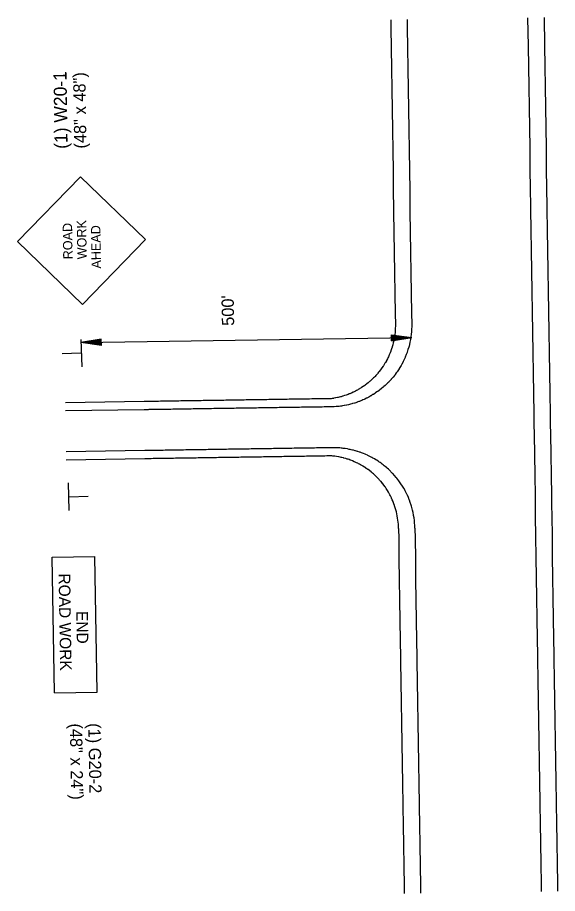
# Model space of a CAD drawing. Extents: x 1770139 to 1773492, y 718230 to 727190.
# Drawn here: x 1771613.4 to 1771877.5, y 720589.3 to 721017.8 of the extents above; entities that cross this region are included whole.
import ezdxf

# ---------------------------------------------------------------- set-up
doc = ezdxf.new("R2010")
doc.units = 0
for name, color, linetype in [('R_Dimension', 7, 'Continuous'), ('R_MOT', 7, 'Continuous'), ('R_Proposed Road', 7, 'Continuous')]:
    doc.layers.add(name, color=color, linetype=linetype)

msp = doc.modelspace()

# ---------------------------------------------------------------- linework, layer by layer
at = {"layer": 'R_Dimension'}
for p, q in [((1771644.44, 720858.82), (1771806.34, 720861.31)), ((1771796.32, 720862.66), (1771806.34, 720861.31)), ((1771796.37, 720859.66), (1771796.32, 720862.66)), ((1771796.32, 720862.41), (1771804.67, 720861.29)), ((1771796.33, 720862.15), (1771802.95, 720861.26)), ((1771796.33, 720861.9), (1771801.29, 720861.23)), ((1771796.34, 720861.65), (1771799.59, 720861.21)), ((1771796.34, 720861.39), (1771797.92, 720861.18)), ((1771796.35, 720860.41), (1771801.29, 720861.23)), ((1771796.35, 720860.67), (1771799.59, 720861.21)), ((1771796.35, 720860.92), (1771797.92, 720861.18)), ((1771796.36, 720859.91), (1771804.67, 720861.29)), ((1771796.36, 720860.16), (1771802.95, 720861.26)), ((1771796.37, 720859.66), (1771806.34, 720861.31)), ((1771654.42, 720860.47), (1771644.44, 720858.82)), ((1771654.47, 720857.47), (1771644.44, 720858.82)), ((1771654.42, 720860.22), (1771646.11, 720858.84)), ((1771654.46, 720857.72), (1771646.11, 720858.84)), ((1771654.43, 720859.97), (1771647.83, 720858.87)), ((1771654.46, 720857.98), (1771647.83, 720858.87)), ((1771654.43, 720859.72), (1771649.5, 720858.9)), ((1771654.45, 720858.23), (1771649.5, 720858.9)), ((1771654.44, 720859.46), (1771651.19, 720858.92)), ((1771654.45, 720858.49), (1771651.19, 720858.92)), ((1771654.44, 720859.21), (1771652.86, 720858.95)), ((1771654.45, 720858.74), (1771652.86, 720858.95)), ((1771654.47, 720857.47), (1771654.42, 720860.47))]:
    msp.add_line(p, q, dxfattribs=at)
at = {"layer": 'R_MOT'}
for p, q in [((1771644.22, 720939.98), (1771613.44, 720908.23)), ((1771644.22, 720939.98), (1771675.95, 720909.19)), ((1771675.95, 720909.19), (1771645.19, 720877.44)), ((1771613.44, 720908.23), (1771645.19, 720877.44)), ((1771644.39, 720860.4), (1771644.82, 720846.9)), ((1771644.41, 720853.68), (1771635.2, 720853.38)), ((1771638.67, 720776.74), (1771638.4, 720790.24)), ((1771638.73, 720783.46), (1771647.95, 720783.64)), ((1771630.46, 720753.86), (1771651.32, 720754.18)), ((1771652.34, 720687.77), (1771651.32, 720754.18)), ((1771631.48, 720687.45), (1771630.46, 720753.86)), ((1771631.48, 720687.45), (1771652.34, 720687.77))]:
    msp.add_line(p, q, dxfattribs=at)
at = {"layer": 'R_Proposed Road'}
for p, q in [((1771675.32, 720829.98), (1771636.83, 720829.39)), ((1771675.38, 720825.98), (1771636.89, 720825.39)), ((1771675.69, 720805.99), (1771637.2, 720805.39)), ((1771675.72, 720801.99), (1771637.26, 720801.39))]:
    msp.add_line(p, q, dxfattribs=at)
for points in [[(1771795.95, 721016.69), (1771796.01, 721012.86), (1771796.16, 721002.86), (1771796.31, 720992.87), (1771796.47, 720982.87), (1771796.62, 720972.87), (1771796.78, 720962.87), (1771796.93, 720952.87), (1771797.08, 720942.87), (1771797.24, 720932.87), (1771797.36, 720924.66), (1771797.36, 720924.65), (1771797.39, 720922.87), (1771797.55, 720912.88), (1771797.7, 720902.88), (1771797.85, 720892.88), (1771798.01, 720882.88), (1771798.16, 720872.88), (1771798.24, 720867.88)], [(1771803.95, 721016.82), (1771804, 721012.99), (1771804.16, 721002.99), (1771804.31, 720992.99), (1771804.47, 720982.99), (1771804.62, 720972.99), (1771804.77, 720962.99), (1771804.93, 720952.99), (1771805.08, 720943), (1771805.24, 720933), (1771805.36, 720924.78), (1771805.36, 720924.78), (1771805.39, 720923), (1771805.55, 720913), (1771805.7, 720903), (1771805.85, 720893), (1771806.01, 720883), (1771806.16, 720873), (1771806.24, 720868)], [(1771862.94, 721017.73), (1771863.15, 721003.9), (1771863.31, 720993.9), (1771863.46, 720983.9), (1771863.61, 720973.9), (1771863.77, 720963.9), (1771863.92, 720953.9), (1771864.08, 720943.9), (1771864.23, 720933.91), (1771864.36, 720925.69), (1771864.36, 720925.69), (1771864.38, 720923.91), (1771864.54, 720913.91), (1771864.69, 720903.91), (1771864.85, 720893.91), (1771865, 720883.91), (1771865.15, 720873.91), (1771865.31, 720863.91), (1771865.46, 720853.91), (1771865.62, 720843.92), (1771865.77, 720833.92), (1771865.92, 720823.92), (1771866, 720818.92), (1771866.08, 720813.92), (1771866.23, 720803.92), (1771866.39, 720793.92), (1771866.54, 720783.92), (1771866.61, 720779.2), (1771866.61, 720779.19), (1771866.69, 720773.92), (1771866.85, 720763.93), (1771867, 720753.93), (1771867.16, 720743.93), (1771867.31, 720733.93), (1771867.47, 720723.93), (1771867.62, 720713.93), (1771867.74, 720705.95), (1771867.77, 720703.93), (1771867.93, 720693.93), (1771868.08, 720683.93), (1771868.24, 720673.94), (1771868.39, 720663.94), (1771868.54, 720653.94), (1771868.7, 720643.94), (1771868.85, 720633.94), (1771868.87, 720632.7), (1771869.01, 720623.94), (1771869.16, 720613.94), (1771869.31, 720603.94), (1771869.47, 720593.95), (1771869.52, 720590.38)], [(1771870.94, 721017.85), (1771871.15, 721004.02), (1771871.3, 720994.02), (1771871.46, 720984.02), (1771871.61, 720974.02), (1771871.77, 720964.03), (1771871.92, 720954.03), (1771872.07, 720944.03), (1771872.23, 720934.03), (1771872.36, 720925.81), (1771872.36, 720925.81), (1771872.38, 720924.03), (1771872.54, 720914.03), (1771872.69, 720904.03), (1771872.85, 720894.03), (1771873, 720884.03), (1771873.15, 720874.04), (1771873.31, 720864.04), (1771873.46, 720854.04), (1771873.62, 720844.04), (1771873.77, 720834.04), (1771873.92, 720824.04), (1771874, 720819.04), (1771874.08, 720814.04), (1771874.23, 720804.04), (1771874.39, 720794.05), (1771874.54, 720784.05), (1771874.61, 720779.32), (1771874.61, 720779.32), (1771874.69, 720774.05), (1771874.85, 720764.05), (1771875, 720754.05), (1771875.16, 720744.05), (1771875.31, 720734.05), (1771875.46, 720724.05), (1771875.62, 720714.05), (1771875.74, 720706.07), (1771875.77, 720704.06), (1771875.93, 720694.06), (1771876.08, 720684.06), (1771876.23, 720674.06), (1771876.39, 720664.06), (1771876.54, 720654.06), (1771876.7, 720644.06), (1771876.85, 720634.06), (1771876.87, 720632.82), (1771877, 720624.07), (1771877.16, 720614.07), (1771877.31, 720604.07), (1771877.47, 720594.07), (1771877.52, 720590.5)], [(1771798.24, 720867.88), (1771798.24, 720866.86), (1771798.21, 720865.83), (1771798.16, 720864.8), (1771798.07, 720863.78), (1771797.97, 720862.82), (1771797.96, 720862.76), (1771797.82, 720861.74), (1771797.64, 720860.73), (1771797.44, 720859.72), (1771797.32, 720859.14), (1771797.22, 720858.71), (1771796.96, 720857.71), (1771796.67, 720856.72), (1771796.65, 720856.63), (1771796.36, 720855.73), (1771796.02, 720854.75), (1771795.96, 720854.61), (1771795.64, 720853.78), (1771795.27, 720852.88), (1771795.24, 720852.82), (1771794.82, 720851.87), (1771794.57, 720851.35), (1771794.36, 720850.93), (1771793.88, 720850), (1771793.86, 720849.97), (1771793.36, 720849.08), (1771793.14, 720848.71), (1771792.82, 720848.18), (1771792.42, 720847.54), (1771792.26, 720847.29), (1771791.69, 720846.46), (1771791.66, 720846.42), (1771791.04, 720845.56), (1771790.96, 720845.45), (1771790.39, 720844.71), (1771790.22, 720844.49), (1771790.06, 720844.3), (1771789.72, 720843.89), (1771789.47, 720843.6), (1771789.02, 720843.08), (1771788.72, 720842.75), (1771788.29, 720842.29), (1771787.96, 720841.95), (1771787.53, 720841.52), (1771787.2, 720841.19), (1771786.76, 720840.77), (1771786.43, 720840.47), (1771785.95, 720840.04), (1771785.66, 720839.78), (1771785.13, 720839.33), (1771784.87, 720839.13), (1771784.28, 720838.65), (1771784.09, 720838.51), (1771783.69, 720838.21), (1771783.4, 720837.99), (1771783.3, 720837.92), (1771782.5, 720837.36), (1771782.5, 720837.36), (1771781.7, 720836.82), (1771781.58, 720836.75), (1771780.89, 720836.32), (1771780.64, 720836.17), (1771780.08, 720835.84), (1771779.68, 720835.61), (1771779.26, 720835.38), (1771778.7, 720835.09), (1771778.44, 720834.96), (1771777.7, 720834.59), (1771777.61, 720834.55), (1771776.78, 720834.17), (1771776.68, 720834.12), (1771775.94, 720833.81), (1771775.64, 720833.69), (1771775.09, 720833.47), (1771774.58, 720833.28), (1771774.24, 720833.16), (1771773.51, 720832.91), (1771773.39, 720832.87), (1771772.52, 720832.6), (1771772.42, 720832.57), (1771771.66, 720832.35), (1771771.32, 720832.26), (1771770.79, 720832.13), (1771770.21, 720831.99), (1771769.91, 720831.93), (1771769.08, 720831.76), (1771769.03, 720831.75), (1771768.14, 720831.59), (1771767.94, 720831.56), (1771767.25, 720831.45), (1771766.8, 720831.39), (1771766.3, 720831.38), (1771765.3, 720831.37), (1771764.3, 720831.35), (1771763.3, 720831.34), (1771762.3, 720831.32), (1771761.3, 720831.31), (1771760.3, 720831.29), (1771759.3, 720831.28), (1771758.3, 720831.26), (1771757.3, 720831.25), (1771756.3, 720831.23), (1771755.3, 720831.22), (1771754.3, 720831.2), (1771753.3, 720831.18), (1771752.3, 720831.17), (1771751.3, 720831.15), (1771750.3, 720831.14), (1771749.3, 720831.12), (1771748.3, 720831.11), (1771747.3, 720831.09), (1771746.3, 720831.08), (1771745.3, 720831.06), (1771744.3, 720831.05), (1771743.3, 720831.03), (1771742.3, 720831.01), (1771741.3, 720831), (1771740.3, 720830.98), (1771739.3, 720830.97), (1771738.3, 720830.95), (1771737.3, 720830.94), (1771736.3, 720830.92), (1771735.3, 720830.91), (1771734.3, 720830.89), (1771733.3, 720830.88), (1771732.3, 720830.86), (1771731.3, 720830.85), (1771730.3, 720830.83), (1771729.3, 720830.81), (1771728.3, 720830.8), (1771727.3, 720830.78), (1771726.3, 720830.77), (1771725.3, 720830.75), (1771724.3, 720830.74), (1771723.3, 720830.72), (1771722.3, 720830.71), (1771721.3, 720830.69), (1771720.3, 720830.68), (1771719.3, 720830.66), (1771718.3, 720830.65), (1771717.3, 720830.63), (1771716.3, 720830.61), (1771715.3, 720830.6), (1771714.3, 720830.58), (1771713.3, 720830.57), (1771712.3, 720830.55), (1771711.3, 720830.54), (1771710.3, 720830.52), (1771709.3, 720830.51), (1771708.3, 720830.49), (1771707.3, 720830.48), (1771706.3, 720830.46), (1771705.3, 720830.44), (1771704.31, 720830.43), (1771703.31, 720830.41), (1771702.31, 720830.4), (1771701.31, 720830.38), (1771700.31, 720830.37), (1771699.31, 720830.35), (1771698.31, 720830.34), (1771697.31, 720830.32), (1771696.31, 720830.31), (1771695.31, 720830.29), (1771694.31, 720830.28), (1771693.31, 720830.26), (1771692.31, 720830.24), (1771691.31, 720830.23), (1771690.31, 720830.21), (1771689.31, 720830.2), (1771688.31, 720830.18), (1771687.31, 720830.17), (1771686.81, 720830.16), (1771686.31, 720830.15), (1771685.31, 720830.14), (1771684.31, 720830.12), (1771683.31, 720830.11), (1771682.31, 720830.09), (1771681.31, 720830.08), (1771680.31, 720830.06), (1771679.31, 720830.04), (1771678.31, 720830.03), (1771677.58, 720830.02), (1771677.31, 720830.01), (1771676.32, 720830), (1771675.32, 720829.98), (1771675.32, 720829.98)], [(1771806.24, 720868), (1771806.24, 720866.72), (1771806.2, 720865.44), (1771806.11, 720864.16), (1771805.99, 720862.88), (1771805.84, 720861.69), (1771805.82, 720861.61), (1771805.62, 720860.35), (1771805.37, 720859.09), (1771805.09, 720857.84), (1771804.91, 720857.13), (1771804.76, 720856.6), (1771804.39, 720855.37), (1771803.99, 720854.15), (1771803.95, 720854.05), (1771803.55, 720852.95), (1771803.06, 720851.76), (1771802.99, 720851.59), (1771802.54, 720850.59), (1771802.02, 720849.5), (1771801.99, 720849.43), (1771801.39, 720848.3), (1771801.05, 720847.68), (1771800.76, 720847.18), (1771800.1, 720846.09), (1771800.08, 720846.05), (1771799.4, 720845.01), (1771799.1, 720844.57), (1771798.66, 720843.96), (1771798.12, 720843.22), (1771797.9, 720842.93), (1771797.14, 720841.98), (1771797.1, 720841.93), (1771796.26, 720840.96), (1771796.16, 720840.83), (1771795.4, 720840.01), (1771795.17, 720839.76), (1771794.96, 720839.54), (1771794.51, 720839.09), (1771794.19, 720838.77), (1771793.59, 720838.19), (1771793.2, 720837.84), (1771792.64, 720837.33), (1771792.21, 720836.97), (1771791.66, 720836.5), (1771791.23, 720836.15), (1771790.66, 720835.7), (1771790.24, 720835.38), (1771789.63, 720834.94), (1771789.25, 720834.67), (1771788.58, 720834.2), (1771788.26, 720833.99), (1771787.5, 720833.51), (1771787.27, 720833.36), (1771786.77, 720833.06), (1771786.41, 720832.84), (1771786.28, 720832.77), (1771785.29, 720832.21), (1771785.29, 720832.21), (1771784.3, 720831.69), (1771784.15, 720831.62), (1771783.3, 720831.21), (1771783, 720831.07), (1771782.31, 720830.76), (1771781.82, 720830.55), (1771781.32, 720830.34), (1771780.63, 720830.07), (1771780.32, 720829.95), (1771779.43, 720829.62), (1771779.33, 720829.59), (1771778.33, 720829.26), (1771778.21, 720829.22), (1771777.34, 720828.96), (1771776.98, 720828.86), (1771776.34, 720828.68), (1771775.74, 720828.53), (1771775.34, 720828.44), (1771774.49, 720828.25), (1771774.35, 720828.22), (1771773.35, 720828.02), (1771773.23, 720828), (1771772.35, 720827.86), (1771771.97, 720827.8), (1771771.35, 720827.72), (1771770.7, 720827.64), (1771770.36, 720827.6), (1771769.42, 720827.51), (1771769.36, 720827.51), (1771768.36, 720827.44), (1771768.14, 720827.43), (1771767.36, 720827.4), (1771766.86, 720827.39), (1771766.36, 720827.38), (1771765.36, 720827.37), (1771764.36, 720827.35), (1771763.36, 720827.34), (1771762.36, 720827.32), (1771761.36, 720827.31), (1771760.36, 720827.29), (1771759.36, 720827.28), (1771758.36, 720827.26), (1771757.36, 720827.25), (1771756.36, 720827.23), (1771755.36, 720827.22), (1771754.36, 720827.2), (1771753.36, 720827.18), (1771752.36, 720827.17), (1771751.36, 720827.15), (1771750.36, 720827.14), (1771749.36, 720827.12), (1771748.36, 720827.11), (1771747.36, 720827.09), (1771746.36, 720827.08), (1771745.36, 720827.06), (1771744.36, 720827.05), (1771743.36, 720827.03), (1771742.36, 720827.02), (1771741.36, 720827), (1771740.36, 720826.98), (1771739.36, 720826.97), (1771738.36, 720826.95), (1771737.36, 720826.94), (1771736.36, 720826.92), (1771735.36, 720826.91), (1771734.36, 720826.89), (1771733.36, 720826.88), (1771732.36, 720826.86), (1771731.36, 720826.85), (1771730.36, 720826.83), (1771729.36, 720826.81), (1771728.36, 720826.8), (1771727.36, 720826.78), (1771726.36, 720826.77), (1771725.36, 720826.75), (1771724.36, 720826.74), (1771723.36, 720826.72), (1771722.36, 720826.71), (1771721.36, 720826.69), (1771720.36, 720826.68), (1771719.36, 720826.66), (1771718.36, 720826.65), (1771717.37, 720826.63), (1771716.37, 720826.61), (1771715.37, 720826.6), (1771714.37, 720826.58), (1771713.37, 720826.57), (1771712.37, 720826.55), (1771711.37, 720826.54), (1771710.37, 720826.52), (1771709.37, 720826.51), (1771708.37, 720826.49), (1771707.37, 720826.48), (1771706.37, 720826.46), (1771705.37, 720826.45), (1771704.37, 720826.43), (1771703.37, 720826.41), (1771702.37, 720826.4), (1771701.37, 720826.38), (1771700.37, 720826.37), (1771699.37, 720826.35), (1771698.37, 720826.34), (1771697.37, 720826.32), (1771696.37, 720826.31), (1771695.37, 720826.29), (1771694.37, 720826.28), (1771693.37, 720826.26), (1771692.37, 720826.24), (1771691.37, 720826.23), (1771690.37, 720826.21), (1771689.37, 720826.2), (1771688.37, 720826.18), (1771687.37, 720826.17), (1771686.87, 720826.16), (1771686.37, 720826.15), (1771685.37, 720826.14), (1771684.37, 720826.12), (1771683.37, 720826.11), (1771682.37, 720826.09), (1771681.37, 720826.08), (1771680.37, 720826.06), (1771679.37, 720826.04), (1771678.37, 720826.03), (1771677.64, 720826.02), (1771677.37, 720826.01), (1771676.38, 720826), (1771675.38, 720825.98)], [(1771807.78, 720768.02), (1771807.74, 720769.3), (1771807.66, 720770.58), (1771807.53, 720771.85), (1771807.37, 720773.13), (1771807.18, 720774.31), (1771807.17, 720774.39), (1771806.92, 720775.65), (1771806.64, 720776.9), (1771806.31, 720778.14), (1771806.11, 720778.84), (1771805.95, 720779.37), (1771805.55, 720780.59), (1771805.11, 720781.79), (1771805.06, 720781.9), (1771804.62, 720782.98), (1771804.11, 720784.15), (1771804.03, 720784.32), (1771803.55, 720785.31), (1771803, 720786.38), (1771802.96, 720786.45), (1771802.33, 720787.56), (1771801.97, 720788.17), (1771801.67, 720788.66), (1771800.97, 720789.74), (1771800.94, 720789.77), (1771800.23, 720790.79), (1771799.92, 720791.22), (1771799.47, 720791.82), (1771798.9, 720792.53), (1771798.67, 720792.82), (1771797.88, 720793.75), (1771797.84, 720793.8), (1771796.98, 720794.74), (1771796.86, 720794.86), (1771796.09, 720795.67), (1771795.85, 720795.9), (1771795.63, 720796.12), (1771795.16, 720796.56), (1771794.83, 720796.87), (1771794.22, 720797.42), (1771793.82, 720797.77), (1771793.24, 720798.25), (1771792.81, 720798.61), (1771792.24, 720799.05), (1771791.79, 720799.39), (1771791.21, 720799.82), (1771790.78, 720800.13), (1771790.16, 720800.56), (1771789.77, 720800.81), (1771789.09, 720801.26), (1771788.76, 720801.46), (1771787.99, 720801.92), (1771787.75, 720802.06), (1771787.25, 720802.34), (1771786.87, 720802.55), (1771786.74, 720802.62), (1771785.74, 720803.14), (1771785.74, 720803.15), (1771784.73, 720803.63), (1771784.58, 720803.7), (1771783.72, 720804.09), (1771783.41, 720804.22), (1771782.71, 720804.51), (1771782.22, 720804.7), (1771781.71, 720804.9), (1771781.02, 720805.15), (1771780.7, 720805.26), (1771779.8, 720805.55), (1771779.7, 720805.58), (1771778.69, 720805.88), (1771778.57, 720805.92), (1771777.69, 720806.15), (1771777.33, 720806.24), (1771776.68, 720806.4), (1771776.08, 720806.53), (1771775.68, 720806.61), (1771774.82, 720806.78), (1771774.68, 720806.8), (1771773.67, 720806.96), (1771773.56, 720806.98), (1771772.67, 720807.1), (1771772.29, 720807.15), (1771771.67, 720807.21), (1771771.01, 720807.27), (1771770.67, 720807.3), (1771769.73, 720807.35), (1771769.67, 720807.36), (1771768.67, 720807.39), (1771768.45, 720807.39), (1771767.67, 720807.4), (1771767.17, 720807.4), (1771766.67, 720807.39), (1771765.67, 720807.37), (1771764.67, 720807.36), (1771763.67, 720807.34), (1771762.67, 720807.33), (1771761.67, 720807.31), (1771760.67, 720807.29), (1771759.67, 720807.28), (1771758.67, 720807.26), (1771757.67, 720807.25), (1771756.67, 720807.23), (1771755.67, 720807.22), (1771754.67, 720807.2), (1771753.67, 720807.19), (1771752.67, 720807.17), (1771751.67, 720807.16), (1771750.67, 720807.14), (1771749.67, 720807.13), (1771748.67, 720807.11), (1771747.67, 720807.09), (1771746.67, 720807.08), (1771745.67, 720807.06), (1771744.67, 720807.05), (1771743.67, 720807.03), (1771742.67, 720807.02), (1771741.67, 720807), (1771740.67, 720806.99), (1771739.67, 720806.97), (1771738.67, 720806.96), (1771737.67, 720806.94), (1771736.67, 720806.93), (1771735.67, 720806.91), (1771734.67, 720806.89), (1771733.67, 720806.88), (1771732.67, 720806.86), (1771731.67, 720806.85), (1771730.67, 720806.83), (1771729.67, 720806.82), (1771728.67, 720806.8), (1771727.67, 720806.79), (1771726.67, 720806.77), (1771725.67, 720806.76), (1771724.67, 720806.74), (1771723.67, 720806.72), (1771722.67, 720806.71), (1771721.67, 720806.69), (1771720.67, 720806.68), (1771719.67, 720806.66), (1771718.67, 720806.65), (1771717.67, 720806.63), (1771716.67, 720806.62), (1771715.67, 720806.6), (1771714.67, 720806.59), (1771713.67, 720806.57), (1771712.67, 720806.56), (1771711.67, 720806.54), (1771710.67, 720806.52), (1771709.67, 720806.51), (1771708.67, 720806.49), (1771707.67, 720806.48), (1771706.67, 720806.46), (1771705.67, 720806.45), (1771704.67, 720806.43), (1771703.67, 720806.42), (1771702.67, 720806.4), (1771701.68, 720806.39), (1771700.68, 720806.37), (1771699.68, 720806.36), (1771698.68, 720806.34), (1771697.68, 720806.32), (1771696.68, 720806.31), (1771695.68, 720806.29), (1771694.68, 720806.28), (1771693.68, 720806.26), (1771692.68, 720806.25), (1771691.68, 720806.23), (1771690.68, 720806.22), (1771689.68, 720806.2), (1771688.68, 720806.19), (1771687.68, 720806.17), (1771687.18, 720806.16), (1771686.68, 720806.15), (1771685.68, 720806.14), (1771684.68, 720806.12), (1771683.68, 720806.11), (1771682.68, 720806.09), (1771681.68, 720806.08), (1771680.68, 720806.06), (1771679.68, 720806.05), (1771678.68, 720806.03), (1771677.95, 720806.02), (1771677.68, 720806.02), (1771676.67, 720806), (1771675.69, 720805.99)], [(1771799.78, 720767.89), (1771799.75, 720768.92), (1771799.69, 720769.94), (1771799.6, 720770.96), (1771799.49, 720771.98), (1771799.35, 720772.94), (1771799.34, 720773), (1771799.17, 720774.02), (1771798.97, 720775.02), (1771798.73, 720776.03), (1771798.59, 720776.6), (1771798.47, 720777.03), (1771798.19, 720778.02), (1771797.87, 720779), (1771797.84, 720779.09), (1771797.53, 720779.98), (1771797.15, 720780.95), (1771797.1, 720781.09), (1771796.75, 720781.9), (1771796.35, 720782.79), (1771796.32, 720782.85), (1771795.87, 720783.79), (1771795.6, 720784.3), (1771795.38, 720784.72), (1771794.87, 720785.63), (1771794.85, 720785.66), (1771794.33, 720786.53), (1771794.1, 720786.9), (1771793.76, 720787.42), (1771793.34, 720788.04), (1771793.17, 720788.29), (1771792.58, 720789.1), (1771792.54, 720789.15), (1771791.9, 720789.99), (1771791.81, 720790.09), (1771791.22, 720790.81), (1771791.04, 720791.02), (1771790.88, 720791.21), (1771790.52, 720791.61), (1771790.27, 720791.89), (1771789.8, 720792.4), (1771789.49, 720792.72), (1771789.04, 720793.17), (1771788.71, 720793.5), (1771788.27, 720793.91), (1771787.92, 720794.23), (1771787.47, 720794.64), (1771787.13, 720794.93), (1771786.64, 720795.34), (1771786.34, 720795.59), (1771785.79, 720796.02), (1771785.54, 720796.22), (1771784.92, 720796.68), (1771784.73, 720796.82), (1771784.33, 720797.1), (1771784.03, 720797.31), (1771783.92, 720797.38), (1771783.11, 720797.92), (1771783.11, 720797.92), (1771782.29, 720798.43), (1771782.17, 720798.5), (1771781.47, 720798.91), (1771781.21, 720799.05), (1771780.64, 720799.36), (1771780.24, 720799.57), (1771779.81, 720799.79), (1771779.24, 720800.07), (1771778.97, 720800.19), (1771778.22, 720800.53), (1771778.13, 720800.57), (1771777.29, 720800.93), (1771777.19, 720800.97), (1771776.44, 720801.26), (1771776.14, 720801.37), (1771775.58, 720801.57), (1771775.07, 720801.75), (1771774.72, 720801.86), (1771773.99, 720802.09), (1771773.86, 720802.12), (1771772.99, 720802.36), (1771772.89, 720802.39), (1771772.12, 720802.58), (1771771.78, 720802.66), (1771771.24, 720802.78), (1771770.66, 720802.9), (1771770.36, 720802.96), (1771769.52, 720803.1), (1771769.47, 720803.11), (1771768.58, 720803.24), (1771768.38, 720803.27), (1771767.68, 720803.35), (1771767.23, 720803.4), (1771766.73, 720803.39), (1771765.73, 720803.37), (1771764.73, 720803.36), (1771763.73, 720803.34), (1771762.73, 720803.33), (1771761.73, 720803.31), (1771760.73, 720803.3), (1771759.73, 720803.28), (1771758.73, 720803.26), (1771757.73, 720803.25), (1771756.73, 720803.23), (1771755.73, 720803.22), (1771754.73, 720803.2), (1771753.73, 720803.19), (1771752.73, 720803.17), (1771751.73, 720803.16), (1771750.73, 720803.14), (1771749.73, 720803.13), (1771748.73, 720803.11), (1771747.73, 720803.1), (1771746.73, 720803.08), (1771745.73, 720803.06), (1771744.73, 720803.05), (1771743.73, 720803.03), (1771742.73, 720803.02), (1771741.73, 720803), (1771740.73, 720802.99), (1771739.73, 720802.97), (1771738.73, 720802.96), (1771737.73, 720802.94), (1771736.73, 720802.93), (1771735.73, 720802.91), (1771734.73, 720802.89), (1771733.73, 720802.88), (1771732.73, 720802.86), (1771731.73, 720802.85), (1771730.73, 720802.83), (1771729.73, 720802.82), (1771728.73, 720802.8), (1771727.73, 720802.79), (1771726.73, 720802.77), (1771725.73, 720802.76), (1771724.73, 720802.74), (1771723.73, 720802.73), (1771722.73, 720802.71), (1771721.73, 720802.69), (1771720.73, 720802.68), (1771719.73, 720802.66), (1771718.73, 720802.65), (1771717.73, 720802.63), (1771716.73, 720802.62), (1771715.74, 720802.6), (1771714.74, 720802.59), (1771713.74, 720802.57), (1771712.74, 720802.56), (1771711.74, 720802.54), (1771710.74, 720802.53), (1771709.74, 720802.51), (1771708.74, 720802.49), (1771707.74, 720802.48), (1771706.74, 720802.46), (1771705.74, 720802.45), (1771704.74, 720802.43), (1771703.74, 720802.42), (1771702.74, 720802.4), (1771701.74, 720802.39), (1771700.74, 720802.37), (1771699.74, 720802.36), (1771698.74, 720802.34), (1771697.74, 720802.32), (1771696.74, 720802.31), (1771695.74, 720802.29), (1771694.74, 720802.28), (1771693.74, 720802.26), (1771692.74, 720802.25), (1771691.74, 720802.23), (1771690.74, 720802.22), (1771689.74, 720802.2), (1771688.74, 720802.19), (1771687.74, 720802.17), (1771687.24, 720802.16), (1771686.74, 720802.16), (1771685.74, 720802.14), (1771684.74, 720802.12), (1771683.74, 720802.11), (1771682.74, 720802.09), (1771681.74, 720802.08), (1771680.74, 720802.06), (1771679.74, 720802.05), (1771678.74, 720802.03), (1771678.01, 720802.02), (1771677.74, 720802.02), (1771676.73, 720802), (1771675.75, 720801.99)], [(1771799.78, 720767.89), (1771799.86, 720762.89), (1771800.01, 720752.89), (1771800.16, 720742.9), (1771800.32, 720732.9), (1771800.47, 720722.9), (1771800.63, 720712.9), (1771800.75, 720704.92), (1771800.78, 720702.9), (1771800.94, 720692.9), (1771801.09, 720682.9), (1771801.24, 720672.9), (1771801.4, 720662.91), (1771801.55, 720652.91), (1771801.71, 720642.91), (1771801.86, 720632.91), (1771801.88, 720631.67), (1771802.01, 720622.91), (1771802.17, 720612.91), (1771802.32, 720602.91), (1771802.48, 720592.91), (1771802.53, 720589.35)], [(1771807.78, 720768.02), (1771807.86, 720763.02), (1771808.01, 720753.02), (1771808.16, 720743.02), (1771808.32, 720733.02), (1771808.47, 720723.02), (1771808.63, 720713.02), (1771808.75, 720705.04), (1771808.78, 720703.02), (1771808.93, 720693.02), (1771809.09, 720683.03), (1771809.24, 720673.03), (1771809.4, 720663.03), (1771809.55, 720653.03), (1771809.7, 720643.03), (1771809.86, 720633.03), (1771809.88, 720631.79), (1771810.01, 720623.03), (1771810.17, 720613.03), (1771810.32, 720603.04), (1771810.47, 720593.04), (1771810.53, 720589.47)]]:
    msp.add_lwpolyline(points, dxfattribs=at)

# ---------------------------------------------------------------- texts
at = {"layer": 'R_Dimension'}
msp.add_text("500'", height=6, rotation=90.8827, dxfattribs=at).set_placement((1771719.4, 720867.06))
at = {"layer": 'R_MOT'}
for s, height, rotation, p in [('(1) W20-1', 6.4, 90.8827, (1771637.96, 720953.65)), ('(48" x 48")', 5.9994, 90.8827, (1771647.17, 720953.79)), ('ROAD', 4.607, 90.8831, (1771640.39, 720899.61)), ('WORK', 4.607, 90.8827, (1771647.3, 720899.62)), (' AHEAD ', 4.607, 90.8833, (1771654.31, 720893.35)), ('ROAD WORK', 5.67, 270.8827, (1771633.52, 720745.87)), ('END', 5.67, 270.8827, (1771642.18, 720727.5)), ('(48" x 24")', 5.9994, 270.8827, (1771639.05, 720672.49)), ('(1) G20-2', 6, 270.8827, (1771648.05, 720672.63))]:
    msp.add_text(s, height=height, rotation=rotation, dxfattribs=at).set_placement(p)

doc.saveas('drawing.dxf')
